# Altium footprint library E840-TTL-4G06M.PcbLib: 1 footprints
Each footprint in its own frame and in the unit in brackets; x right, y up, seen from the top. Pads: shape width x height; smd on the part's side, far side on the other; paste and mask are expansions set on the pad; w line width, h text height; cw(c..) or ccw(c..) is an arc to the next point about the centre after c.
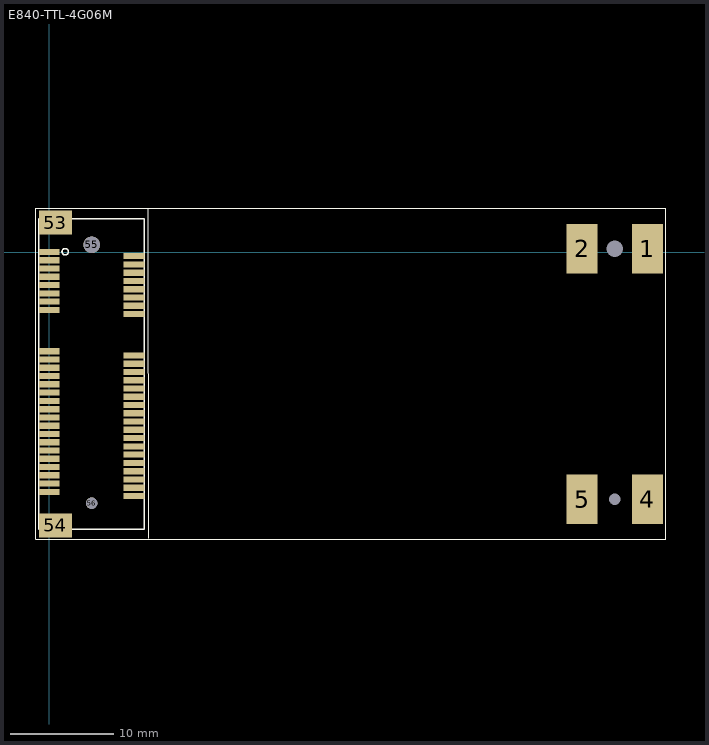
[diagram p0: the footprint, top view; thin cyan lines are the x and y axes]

## E840-TTL-4G06M [mm]
pads (62):
  rect 2x0.6 smd: 1(0,0) 2(8.2,-0.4) 3(0,-0.8) 4(8.2,-1.2) 5(0,-1.6) 6(8.2,-2) 7(0,-2.4) 8(8.2,-2.8) 9(0,-3.2) 10(8.2,-3.6) 11(0,-4) 12(8.2,-4.4) 13(0,-4.8) 14(8.2,-5.2) 15(0,-5.6) 16(8.2,-6) 17(0,-9.6) 18(8.2,-10) 19(0,-10.4) 20(8.2,-10.8) 21(0,-11.2) 22(8.2,-11.6) 23(0,-12) 24(8.2,-12.4) 25(0,-12.8) 26(8.2,-13.2) 27(0,-13.6) 28(8.2,-14) 29(0,-14.4) 30(8.2,-14.8) 31(0,-15.2) 32(8.2,-15.6) 33(0,-16) 34(8.2,-16.4) 35(0,-16.8) 36(8.2,-17.2) 37(0,-17.6) 38(8.2,-18) 39(0,-18.4) 40(8.2,-18.8) 41(0,-19.2) 42(8.2,-19.6) 43(0,-20) 44(8.2,-20.4) 45(0,-20.8) 46(8.2,-21.2) 47(0,-21.6) 48(8.2,-22) 49(0,-22.4) 50(8.2,-22.8) 51(0,-23.2) 52(8.2,-23.6)
  rect 3x4.8 smd: 1(57.85,0.3) 2(51.55,0.3) 4(57.85,-23.9) 5(51.55,-23.9)
  round 0 hole 1.6: 3(54.7,0.3)
  round 0 hole 1.1: 6(54.7,-23.9)
  rect 3.2x2.3 smd: 53(0.6,2.85) 54(0.6,-26.45)
  round 1.6 hole 1.6: 55(4.1,0.7)
  round 1.1 hole 1.1: 56(4.1,-24.3)
Top Overlay:
  circle w0.15: c1.54,0.025 r0.308
  lines w0.1: 9.549,4.165 9.568,-27.684 ; -1.3,-27.778 59.649,-27.778 59.649,4.233 -1.3,4.233 -1.3,-27.778
  lines w0.15: -1,-26.8 9.2,-26.8 9.2,3.2 -1,3.2 -1,-26.8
